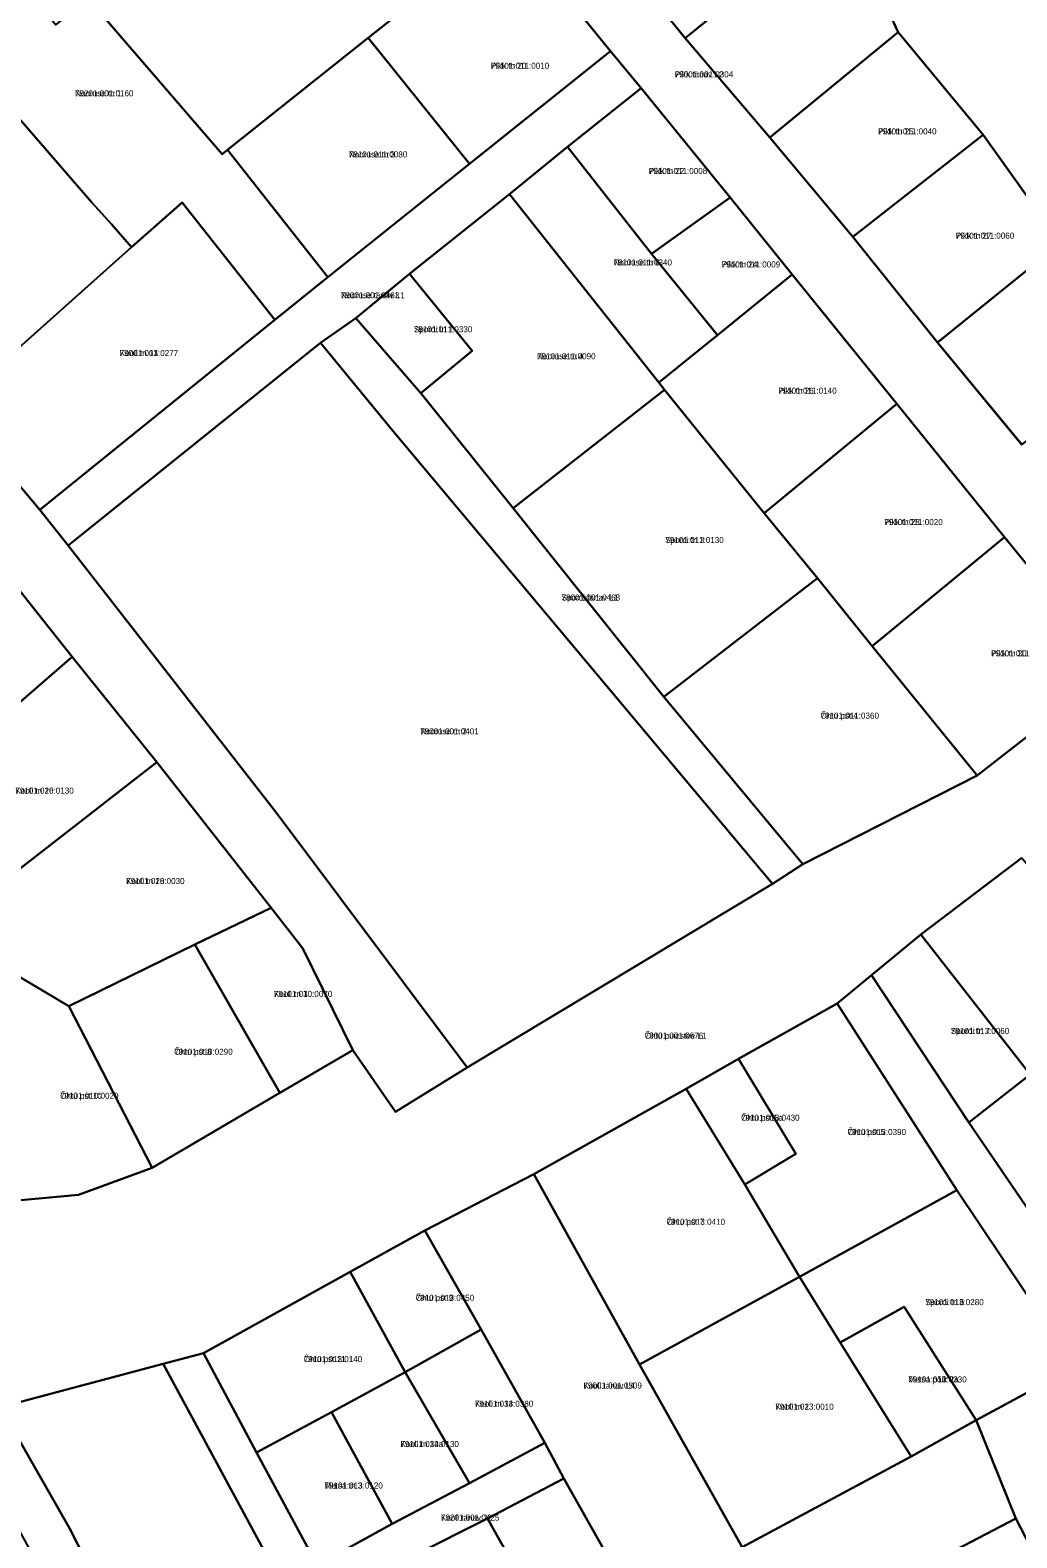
# Model space of a CAD drawing. Extents: x 587616 to 632239, y 6547421 to 6574977.
# Drawn here: x 611903.8 to 612148.7, y 6570404.3 to 6570778.6 of the extents above; entities that cross this region are included whole.
import ezdxf

# ---------------------------------------------------------------- set-up
doc = ezdxf.new("R2010")
doc.units = 0
for name, color, linetype in [('L_AADRESS', 7, 'Continuous'), ('PIIR', 7, 'Continuous'), ('TUNNUS', 7, 'Continuous')]:
    doc.layers.add(name, color=color, linetype=linetype)

msp = doc.modelspace()

# ---------------------------------------------------------------- linework, layer by layer
at = {"layer": 'PIIR'}
for points in [[(612060.8, 6570783.53), (612091.71, 6570808.97), (612115.95, 6570828.78), (612118.98, 6570836.2), (612122.84, 6570822.86), (612102.75, 6570806.21), (612066.38, 6570776.63)], [(611870.89, 6570828.68), (611877.64, 6570830.43), (611895.46, 6570809.81), (611895.14, 6570798.67), (611910.25, 6570779.94), (611918.35, 6570786.34), (611951.45, 6570747.78), (611952.8, 6570748.83), (611977.71, 6570717.27), (611964.58, 6570706.66), (611941.59, 6570735.81), (611929, 6570724.67), (611924, 6570730.41), (611919.17, 6570735.8), (611852.26, 6570813.19)], [(611963.53, 6570832.94), (611985.77, 6570804.41), (611999.85, 6570786.38), (611987.72, 6570776.69), (611952.8, 6570748.83), (611951.45, 6570747.78), (611918.35, 6570786.34), (611930.87, 6570796.5), (611925.75, 6570803.2), (611937.66, 6570812.53)], [(611798.58, 6570787.55), (611841.97, 6570817.85), (611845.88, 6570821.05), (611852.26, 6570813.19), (611919.17, 6570735.8), (611924, 6570730.41), (611929, 6570724.67), (611884.61, 6570685.13), (611828.55, 6570752.1)], [(612102.75, 6570806.21), (612120.84, 6570784.23), (612117.59, 6570781.67), (612119.26, 6570778.1), (612087.4, 6570751.95), (612066.38, 6570776.63)], [(612117.59, 6570781.67), (612120.84, 6570784.23), (612141.22, 6570801), (612143.73, 6570803.06), (612188.21, 6570749.24), (612159.57, 6570725.67), (612140.34, 6570752.58), (612119.26, 6570778.1)], [(611987.72, 6570776.69), (611999.85, 6570786.38), (612007.31, 6570792.42), (612011.47, 6570787.13), (612020.29, 6570782.94), (612032.19, 6570792.61), (612047.87, 6570773.38), (612012.88, 6570745.4)], [(612087.4, 6570751.95), (612119.26, 6570778.1), (612140.34, 6570752.58), (612107.97, 6570727.29)], [(611987.72, 6570776.69), (612012.88, 6570745.4), (611977.71, 6570717.27), (611952.8, 6570748.83)], [(611906.25, 6570659.52), (611964.58, 6570706.66), (611977.71, 6570717.27), (612012.88, 6570745.4), (612047.87, 6570773.38), (612055.47, 6570764.16), (612037.18, 6570749.6), (612022.8, 6570737.83), (611998.02, 6570718.04), (611984.64, 6570707.04), (611975.86, 6570700.91), (611913.25, 6570650.66)], [(612055.47, 6570764.16), (612077.53, 6570737.05), (612058, 6570723.08), (612037.18, 6570749.6)], [(612107.97, 6570727.29), (612140.34, 6570752.58), (612159.57, 6570725.67), (612129.01, 6570701.02)], [(612037.18, 6570749.6), (612058, 6570723.08), (612074.43, 6570702.89), (612059.89, 6570691.08), (612022.8, 6570737.83)], [(612129.01, 6570701.02), (612159.57, 6570725.67), (612188.21, 6570749.24), (612209.63, 6570724.02), (612176.28, 6570696.99), (612149.92, 6570675.7)], [(612000.76, 6570688.47), (612013.51, 6570698.96), (611998.02, 6570718.04), (612022.8, 6570737.83), (612059.89, 6570691.08), (612061.3, 6570689.31), (612023.69, 6570659.92)], [(612077.53, 6570737.05), (612092.94, 6570717.94), (612074.43, 6570702.89), (612058, 6570723.08)], [(611884.61, 6570685.13), (611929, 6570724.67), (611941.59, 6570735.81), (611964.58, 6570706.66), (611906.25, 6570659.52)], [(611998.02, 6570718.04), (612013.51, 6570698.96), (612000.76, 6570688.47), (611984.64, 6570707.04)], [(612061.3, 6570689.31), (612059.89, 6570691.08), (612074.43, 6570702.89), (612092.94, 6570717.94), (612118.88, 6570685.83), (612085.98, 6570658.7)], [(611984.64, 6570707.04), (612000.76, 6570688.47), (612023.69, 6570659.92), (612061.09, 6570613.09), (612095.61, 6570571.5), (612088.08, 6570566.66), (611993.82, 6570679.11), (611975.86, 6570700.91)], [(611913.25, 6570650.66), (611975.86, 6570700.91), (611993.82, 6570679.11), (612088.08, 6570566.66), (612012.28, 6570521.05), (611964.89, 6570584.37)], [(612023.69, 6570659.92), (612061.3, 6570689.31), (612085.98, 6570658.7), (612099.25, 6570642.5), (612061.09, 6570613.09)], [(612099.25, 6570642.5), (612085.98, 6570658.7), (612118.88, 6570685.83), (612145.66, 6570652.66), (612112.78, 6570625.63)], [(612112.78, 6570625.63), (612145.66, 6570652.66), (612172.56, 6570619.75), (612138.89, 6570593.53)], [(611854.21, 6570570.85), (611835.95, 6570581.38), (611872.85, 6570633.18), (611893, 6570649.7), (611914.28, 6570623)], [(612061.09, 6570613.09), (612099.25, 6570642.5), (612112.78, 6570625.63), (612138.89, 6570593.53), (612095.61, 6570571.5)], [(611864.16, 6570565.04), (611854.21, 6570570.85), (611914.28, 6570623), (611935.27, 6570596.87), (611881.47, 6570555.03)], [(611892.72, 6570548.51), (611881.47, 6570555.03), (611935.27, 6570596.87), (611963.63, 6570560.69), (611944.7, 6570551.55), (611913.41, 6570536.27)], [(612149.91, 6570573.11), (612177.38, 6570539.87), (612152.02, 6570519.33), (612124.89, 6570554.03)], [(611963.63, 6570560.69), (611971.5, 6570550.55), (611983.94, 6570525.34), (611965.79, 6570514.73), (611944.7, 6570551.55)], [(612124.89, 6570554.03), (612152.02, 6570519.33), (612136.81, 6570507.4), (612112.61, 6570543.92)], [(611944.7, 6570551.55), (611965.79, 6570514.73), (611934.14, 6570496.1), (611913.41, 6570536.27)], [(611915.84, 6570489.39), (611900.6, 6570488.03), (611888.41, 6570540.48), (611892.72, 6570548.51), (611913.41, 6570536.27), (611934.14, 6570496.1)], [(612112.61, 6570543.92), (612136.81, 6570507.4), (612161.73, 6570470.88), (612184.15, 6570437.16), (612167.4, 6570424.9), (612181.22, 6570398.11), (612186.31, 6570388.84), (612205.21, 6570353.42), (612216.59, 6570332.51), (612234.85, 6570298.35), (612237.49, 6570293.27), (612265.26, 6570241.2), (612278.95, 6570215.43), (612291.6, 6570192.74), (612265.23, 6570183.71), (612148.42, 6570409.02), (612138.63, 6570433.49), (612161.48, 6570445.8), (612161.98, 6570448.42), (612133.77, 6570490.58), (612104.15, 6570536.91)], [(612136.81, 6570507.4), (612152.02, 6570519.33), (612177.38, 6570539.87), (612204.05, 6570505.64), (612184.19, 6570489.33), (612161.73, 6570470.88)], [(612081.19, 6570491.97), (612093.88, 6570499.59), (612079.64, 6570523.21), (612104.15, 6570536.91), (612133.77, 6570490.58), (612094.74, 6570469.05)], [(612079.64, 6570523.21), (612093.88, 6570499.59), (612081.19, 6570491.97), (612066.67, 6570515.71)], [(612028.84, 6570494.58), (612066.67, 6570515.71), (612081.19, 6570491.97), (612094.74, 6570469.05), (612055.07, 6570447.27)], [(612015.78, 6570455.95), (612001.79, 6570480.58), (612028.84, 6570494.58), (612055.07, 6570447.27), (612080.52, 6570401.98), (612053.81, 6570387.84), (612036.24, 6570418.98), (612031.54, 6570427.88)], [(612104.87, 6570452.75), (612094.74, 6570469.05), (612133.77, 6570490.58), (612161.98, 6570448.42), (612161.48, 6570445.8), (612138.63, 6570433.49), (612120.77, 6570461.62)], [(611996.87, 6570445.38), (611983.28, 6570470.3), (612001.79, 6570480.58), (612015.78, 6570455.95)], [(611978.6, 6570435.48), (611960.02, 6570425.48), (611946.82, 6570450.07), (611983.28, 6570470.3), (611996.87, 6570445.38)], [(612094.74, 6570469.05), (612104.87, 6570452.75), (612122.44, 6570424.49), (612080.52, 6570401.98), (612055.07, 6570447.27)], [(612120.77, 6570461.62), (612138.63, 6570433.49), (612122.44, 6570424.49), (612104.87, 6570452.75)], [(611996.87, 6570445.38), (612015.78, 6570455.95), (612031.54, 6570427.88), (612012.88, 6570417.82)], [(611936.87, 6570447.43), (611946.82, 6570450.07), (611960.02, 6570425.48), (611975.06, 6570397.45), (611979.22, 6570389.2), (611996.9, 6570357.38), (612001.12, 6570349.45), (611991.95, 6570345.42)], [(611896.46, 6570436.66), (611936.87, 6570447.43), (611991.95, 6570345.42), (611974.57, 6570338.44), (611961.86, 6570335.51), (611952.8, 6570337.06), (611946.28, 6570342.51), (611913.62, 6570406.64)], [(611978.6, 6570435.48), (611996.87, 6570445.38), (612012.88, 6570417.82), (611993.71, 6570407.74)], [(611961.86, 6570335.51), (611948.58, 6570317.98), (611924.95, 6570361.88), (611902.63, 6570403.52), (611891.51, 6570423.45), (611885.66, 6570433.8), (611896.46, 6570436.66), (611913.62, 6570406.64), (611946.28, 6570342.51), (611952.8, 6570337.06)], [(612138.63, 6570433.49), (612148.42, 6570409.02), (612037.77, 6570351.19), (611971.98, 6570323.85), (611953.29, 6570310.71), (611910.25, 6570286.19), (611905.05, 6570294.2), (611929.8, 6570307.69), (611948.58, 6570317.98), (611961.86, 6570335.51), (611974.57, 6570338.44), (611991.95, 6570345.42), (612001.12, 6570349.45), (611996.9, 6570357.38), (612015.81, 6570367.42), (612034.97, 6570377.58), (612053.81, 6570387.84), (612080.52, 6570401.98), (612122.44, 6570424.49)], [(611960.02, 6570425.48), (611978.6, 6570435.48), (611993.71, 6570407.74), (611975.06, 6570397.45)], [(611998.72, 6570399.68), (611979.22, 6570389.2), (611975.06, 6570397.45), (611993.71, 6570407.74), (612012.88, 6570417.82), (612031.54, 6570427.88), (612036.24, 6570418.98), (612017.36, 6570409.05)], [(612034.97, 6570377.58), (612017.36, 6570409.05), (612036.24, 6570418.98), (612053.81, 6570387.84)], [(611998.72, 6570399.68), (612017.36, 6570409.05), (612034.97, 6570377.58), (612015.81, 6570367.42)], [(612037.77, 6570351.19), (612148.42, 6570409.02), (612265.23, 6570183.71), (612236.72, 6570173.91), (612180.28, 6570154.47), (612152.3, 6570146.39), (612138.93, 6570144.06)]]:
    msp.add_lwpolyline(points, close=True, dxfattribs=at)
for points in [[(612172.56, 6570619.75), (612145.66, 6570652.66), (612118.88, 6570685.83), (612092.94, 6570717.94), (612077.53, 6570737.05), (612055.47, 6570764.16), (612047.87, 6570773.38), (612032.19, 6570792.61)], [(611798.58, 6570787.55), (611828.55, 6570752.1), (611884.61, 6570685.13), (611906.25, 6570659.52), (611913.25, 6570650.66), (611964.89, 6570584.37), (612012.28, 6570521.05), (611994.5, 6570510.05), (611983.94, 6570525.34), (611971.5, 6570550.55), (611963.63, 6570560.69), (611935.27, 6570596.87), (611914.28, 6570623), (611893, 6570649.7), (611874.8, 6570671.59), (611868.94, 6570678.98), (611851.48, 6570700.46), (611833.58, 6570720.86), (611819.83, 6570737.75), (611806.32, 6570754.18), (611792.49, 6570770.77), (611779.4, 6570786.19)], [(612060.8, 6570783.53), (612066.38, 6570776.63), (612087.4, 6570751.95), (612107.97, 6570727.29), (612129.01, 6570701.02), (612149.96, 6570675.66)], [(611900.6, 6570488.03), (611915.84, 6570489.39), (611934.14, 6570496.1), (611965.79, 6570514.73), (611983.94, 6570525.34), (611994.5, 6570510.05), (612012.28, 6570521.05), (612088.08, 6570566.66), (612095.61, 6570571.5), (612138.89, 6570593.53), (612172.56, 6570619.75)], [(612149.91, 6570573.11), (612124.89, 6570554.03), (612112.61, 6570543.92), (612104.15, 6570536.91), (612079.64, 6570523.21), (612066.67, 6570515.71), (612028.84, 6570494.58), (612001.79, 6570480.58), (611983.28, 6570470.3), (611946.82, 6570450.07), (611936.87, 6570447.43), (611896.46, 6570436.66)]]:
    msp.add_lwpolyline(points, dxfattribs=at)

# ---------------------------------------------------------------- texts
at = {"layer": 'L_AADRESS'}
for s, p in [('Pikk tn 20', (612018.15, 6570769)), ('Pikk tänav L2', (612063.81, 6570766.86)), ('Nooruse tn 1', (611914.98, 6570762.16)), ('Pikk tn 25', (612114.28, 6570752.7)), ('Nooruse tn 3', (611982.93, 6570746.98)), ('Pikk tn 22', (612057.36, 6570742.87)), ('Pikk tn 27', (612133.56, 6570726.8)), ('Nooruse tn 6', (612048.61, 6570720.16)), ('Pikk tn 24', (612075.47, 6570719.66)), ('Nooruse tänav L1', (611980.96, 6570712.02)), ('Spordi tn 1', (611999.07, 6570703.58)), ('Kooli tn 13', (611926.07, 6570697.66)), ('Nooruse tn 4', (612029.66, 6570696.88)), ('Pikk tn 26', (612089.48, 6570688.32)), ('Pikk tn 28', (612115.82, 6570655.72)), ('Spordi tn 3', (612061.47, 6570651.24)), ('Spordi tänav L1', (612035.73, 6570636.97)), ('Pikk tn 30', (612142.33, 6570623.1)), ('Õhtu pst 4', (612099.99, 6570607.65)), ('Nooruse tn 2', (612000.66, 6570603.76)), ('Kooli tn 26', (611900.15, 6570589.02)), ('Kooli tn 28', (611927.66, 6570566.57)), ('Kooli tn 30', (611964.32, 6570538.55)), ('Spordi tn 7', (612132.32, 6570529.36)), ('Õhtu puiestee L1', (612056.37, 6570528.21)), ('Õhtu pst 8', (611939.6, 6570524.19)), ('Õhtu pst 10', (611911.27, 6570513.26)), ('Õhtu pst 5a', (612080.28, 6570507.81)), ('Õhtu pst 5', (612106.71, 6570504.28)), ('Õhtu pst 7', (612061.79, 6570481.97)), ('Õhtu pst 9', (611999.53, 6570463.1)), ('Spordi tn 6', (612125.98, 6570462.03)), ('Õhtu pst 11', (611971.75, 6570447.89)), ('Metsa põik 2a', (612121.75, 6570442.84)), ('Kooli tänav L4', (612041.16, 6570441.32)), ('Kooli tn 34', (612014.2, 6570436.8)), ('Kooli tn 23', (612088.75, 6570436.08)), ('Kooli tn 34a', (611995.74, 6570426.79)), ('Metsa tn 3', (611976.87, 6570416.5)), ('Kooli tänav J2', (612005.79, 6570408.54))]:
    msp.add_text(s, height=1.5, dxfattribs=at).set_placement(p)
at = {"layer": 'TUNNUS'}
for s, p in [('79101:011:0010', (612018.15, 6570769)), ('79001:001:0304', (612063.81, 6570766.86)), ('79201:001:0160', (611914.98, 6570762.16)), ('79101:011:0040', (612114.28, 6570752.7)), ('79101:011:0080', (611982.93, 6570746.98)), ('79101:011:0008', (612057.36, 6570742.87)), ('79101:011:0060', (612133.56, 6570726.8)), ('79101:011:0340', (612048.61, 6570720.16)), ('79101:011:0009', (612075.47, 6570719.66)), ('79001:001:0463', (611980.96, 6570712.02)), ('79101:011:0330', (611999.07, 6570703.58)), ('79001:001:0277', (611926.07, 6570697.66)), ('79101:011:0090', (612029.66, 6570696.88)), ('79101:011:0140', (612089.48, 6570688.32)), ('79101:011:0020', (612115.82, 6570655.72)), ('79101:011:0130', (612061.47, 6570651.24)), ('79001:001:0468', (612035.73, 6570636.97)), ('79101:011:0170', (612142.33, 6570623.1)), ('79101:011:0360', (612099.99, 6570607.65)), ('79001:001:0401', (612000.66, 6570603.76)), ('79101:010:0130', (611900.15, 6570589.02)), ('79101:010:0030', (611927.66, 6570566.57)), ('79101:010:0070', (611964.32, 6570538.55)), ('79101:013:0060', (612132.32, 6570529.36)), ('79001:001:0676', (612056.37, 6570528.21)), ('79101:010:0290', (611939.6, 6570524.19)), ('79101:010:0020', (611911.27, 6570513.26)), ('79101:013:0430', (612080.28, 6570507.81)), ('79101:013:0390', (612106.71, 6570504.28)), ('79101:013:0410', (612061.79, 6570481.97)), ('79101:013:0450', (611999.53, 6570463.1)), ('79101:013:0280', (612125.98, 6570462.03)), ('79101:013:0140', (611971.75, 6570447.89)), ('79101:013:0330', (612121.75, 6570442.84)), ('79001:001:0509', (612041.16, 6570441.32)), ('79101:013:0380', (612014.2, 6570436.8)), ('79101:013:0010', (612088.75, 6570436.08)), ('79101:013:0130', (611995.74, 6570426.79)), ('79101:013:0120', (611976.87, 6570416.5)), ('79201:001:0425', (612005.79, 6570408.54))]:
    msp.add_text(s, height=1.5, dxfattribs=at).set_placement(p)

doc.saveas('drawing.dxf')
